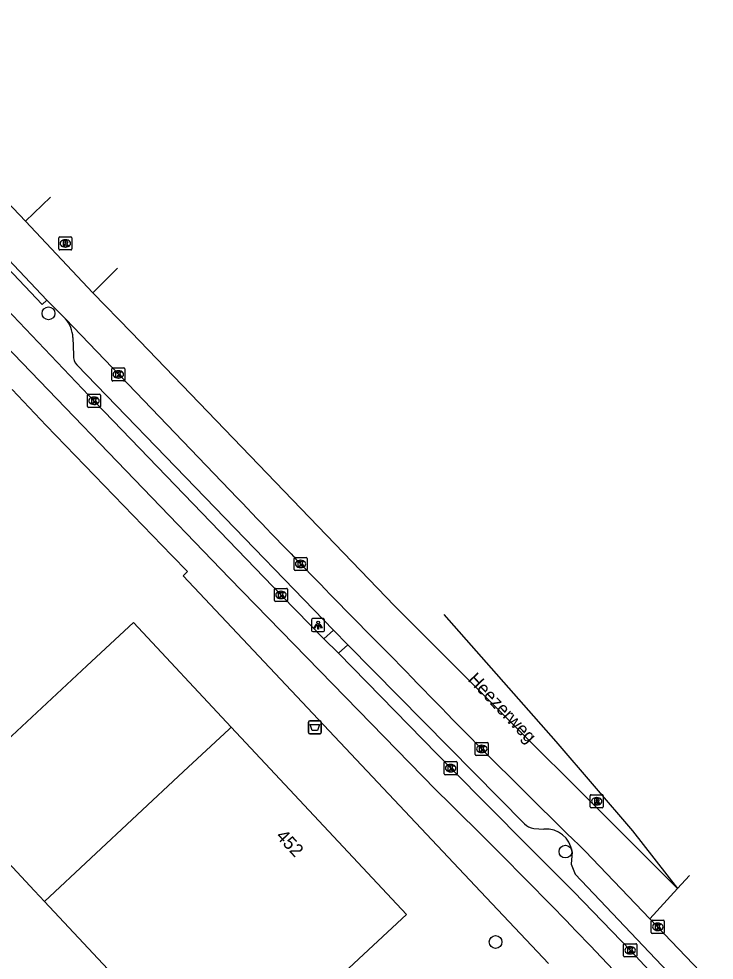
# Model space of a CAD drawing. Extents: x 162675 to 163482, y 379761 to 381227.
# Drawn here: x 163172.9 to 163226.1, y 381140.7 to 381212.8 of the extents above; entities that cross this region are included whole.
import ezdxf

# ---------------------------------------------------------------- set-up
doc = ezdxf.new("R2010")
doc.units = 0
for name, color, linetype in [('IMGEO_Afvalbak', 7, 'Continuous'), ('IMGEO_Boom', 7, 'Continuous'), ('IMGEO_Fietspad_gesloten', 7, 'Continuous'), ('IMGEO_Kolk', 7, 'Continuous'), ('IMGEO_Lichtpunt', 7, 'Continuous'), ('IMGEO_Openbare_ruimte_label', 7, 'Continuous'), ('IMGEO_Pand', 7, 'Continuous'), ('IMGEO_Pand_nummerreeks', 7, 'Continuous'), ('IMGEO_Parkeervlak_open', 7, 'Continuous'), ('IMGEO_Rijbaan_lokaal_gesloten', 7, 'Continuous'), ('IMGEO_Rioolput', 7, 'Continuous'), ('IMGEO_Voetpad_open', 7, 'Continuous')]:
    doc.layers.add(name, color=color, linetype=linetype)

msp = doc.modelspace()

# ---------------------------------------------------------------- linework, layer by layer
at = {"layer": 'IMGEO_Afvalbak'}
for p, q in [((163195.065, 381158.112), (163195.065, 381158.912)), ((163195.065, 381158.912), (163195.065, 381158.112)), ((163195.165, 381159.012), (163195.955, 381159.012)), ((163195.955, 381159.012), (163195.165, 381159.012)), ((163196.055, 381158.912), (163196.055, 381158.112)), ((163196.055, 381158.112), (163196.055, 381158.912)), ((163195.955, 381158.012), (163195.165, 381158.012)), ((163195.165, 381158.012), (163195.955, 381158.012))]:
    msp.add_line(p, q, dxfattribs=at)
msp.add_lwpolyline([(163195.208, 381158.726), (163195.912, 381158.726), (163195.763, 381158.256), (163195.357, 381158.256), (163195.208, 381158.726)], dxfattribs=at)
for centre, start, end in [((163195.165, 381158.912), 90, 180), ((163195.165, 381158.912), 90, 180), ((163195.955, 381158.912), 0, 90), ((163195.955, 381158.912), 360, 90), ((163195.165, 381158.112), 180, 270), ((163195.165, 381158.112), 180, 270), ((163195.955, 381158.112), 270, 0), ((163195.955, 381158.112), 270, 0)]:
    msp.add_arc(centre, 0.1, start, end, dxfattribs=at)
at = {"layer": 'IMGEO_Boom'}
for centre in [(163175.169, 381190.207), (163214.744, 381148.989), (163209.396, 381142.069)]:
    msp.add_circle(centre, 0.489, dxfattribs=at)
at = {"layer": 'IMGEO_Fietspad_gesloten'}
for points in [[(163196.244, 381165.283), (163193.035, 381168.573), (163178.747, 381183.413), (163164.651, 381198.209)], [(163204.799, 381153.749), (163189.021, 381169.931), (163167.194, 381192.6), (163163.242, 381196.786)], [(163196.244, 381165.283), (163197.359, 381164.18)], [(163254.065, 381104.768), (163246.857, 381112.468), (163234.1, 381126.005), (163219.744, 381141.388), (163215.395, 381145.9), (163211.799, 381149.501), (163205.99, 381155.343), (163197.359, 381164.18)], [(163442.528, 380900.205), (163438.582, 380904.399), (163403.356, 380942.043), (163381.324, 380965.637), (163349.187, 381000), (163303.348, 381049.029), (163302.54, 381049.896), (163269.7, 381085.146), (163222.96, 381135.118), (163217.057, 381141.357)]]:
    msp.add_lwpolyline(points, dxfattribs=at)
msp.add_arc((162825.277, 380766.073), 542.522, 43.76808, 45.60899, dxfattribs=at)
at = {"layer": 'IMGEO_Kolk'}
for p, q in [((163180.013, 381185.102), (163180.013, 381185.954)), ((163180.088, 381186.028), (163180.94, 381186.028)), ((163180.501, 381185.808), (163180.526, 381185.808)), ((163181.014, 381185.954), (163181.014, 381185.102)), ((163180.94, 381185.028), (163180.088, 381185.028)), ((163180.524, 381185.248), (163180.499, 381185.248)), ((163178.154, 381183.085), (163178.154, 381183.937)), ((163178.229, 381184.011), (163179.081, 381184.011)), ((163178.642, 381183.791), (163178.667, 381183.791)), ((163179.155, 381183.937), (163179.155, 381183.085)), ((163179.081, 381183.011), (163178.229, 381183.011)), ((163178.665, 381183.231), (163178.64, 381183.231)), ((163193.966, 381170.593), (163193.966, 381171.445)), ((163194.041, 381171.519), (163194.893, 381171.519)), ((163194.454, 381171.299), (163194.479, 381171.299)), ((163194.967, 381171.445), (163194.967, 381170.593)), ((163194.893, 381170.519), (163194.041, 381170.519)), ((163194.477, 381170.739), (163194.452, 381170.739)), ((163192.462, 381168.223), (163192.462, 381169.075)), ((163192.537, 381169.149), (163193.389, 381169.149)), ((163193.463, 381169.075), (163193.463, 381168.223)), ((163192.973, 381168.369), (163192.948, 381168.369)), ((163192.95, 381168.929), (163192.975, 381168.929)), ((163193.389, 381168.149), (163192.537, 381168.149)), ((163207.837, 381156.427), (163207.837, 381157.279)), ((163207.912, 381157.353), (163208.764, 381157.353)), ((163208.325, 381157.133), (163208.35, 381157.133)), ((163208.838, 381157.279), (163208.838, 381156.427)), ((163208.764, 381156.353), (163207.912, 381156.353)), ((163208.348, 381156.573), (163208.323, 381156.573)), ((163205.455, 381154.953), (163205.455, 381155.805)), ((163205.53, 381155.879), (163206.382, 381155.879)), ((163205.943, 381155.659), (163205.968, 381155.659)), ((163206.456, 381155.805), (163206.456, 381154.953)), ((163206.382, 381154.879), (163205.53, 381154.879)), ((163205.966, 381155.099), (163205.941, 381155.099)), ((163221.312, 381142.803), (163221.312, 381143.655)), ((163221.387, 381143.729), (163222.239, 381143.729)), ((163221.8, 381143.509), (163221.825, 381143.509)), ((163222.313, 381143.655), (163222.313, 381142.803)), ((163222.239, 381142.729), (163221.387, 381142.729)), ((163221.823, 381142.949), (163221.798, 381142.949)), ((163219.196, 381141.013), (163219.196, 381141.865)), ((163219.271, 381141.939), (163220.123, 381141.939)), ((163219.684, 381141.719), (163219.709, 381141.719)), ((163220.197, 381141.865), (163220.197, 381141.013)), ((163220.123, 381140.939), (163219.271, 381140.939)), ((163219.707, 381141.159), (163219.682, 381141.159))]:
    msp.add_line(p, q, dxfattribs=at)
for points in [[(163180.013, 381185.102), (163180.013, 381185.954)], [(163180.088, 381186.028), (163180.94, 381186.028)], [(163180.334, 381185.728), (163180.457, 381185.728), (163180.457, 381185.577), (163180.587, 381185.728), (163180.751, 381185.728), (163180.605, 381185.577), (163180.758, 381185.328), (163180.606, 381185.328), (163180.521, 381185.492), (163180.457, 381185.425), (163180.457, 381185.328), (163180.334, 381185.328), (163180.334, 381185.728)], [(163181.014, 381185.954), (163181.014, 381185.102)], [(163180.94, 381185.028), (163180.088, 381185.028)], [(163178.154, 381183.085), (163178.154, 381183.937)], [(163178.229, 381184.011), (163179.081, 381184.011)], [(163178.475, 381183.711), (163178.598, 381183.711), (163178.598, 381183.56), (163178.728, 381183.711), (163178.892, 381183.711), (163178.746, 381183.56), (163178.899, 381183.311), (163178.747, 381183.311), (163178.662, 381183.475), (163178.598, 381183.408), (163178.598, 381183.311), (163178.475, 381183.311), (163178.475, 381183.711)], [(163179.155, 381183.937), (163179.155, 381183.085)], [(163179.081, 381183.011), (163178.229, 381183.011)], [(163193.966, 381170.593), (163193.966, 381171.445)], [(163194.041, 381171.519), (163194.893, 381171.519)], [(163194.287, 381171.219), (163194.41, 381171.219), (163194.41, 381171.068), (163194.54, 381171.219), (163194.704, 381171.219), (163194.558, 381171.068), (163194.711, 381170.819), (163194.559, 381170.819), (163194.474, 381170.983), (163194.41, 381170.916), (163194.41, 381170.819), (163194.287, 381170.819), (163194.287, 381171.219)], [(163194.967, 381171.445), (163194.967, 381170.593)], [(163194.893, 381170.519), (163194.041, 381170.519)], [(163192.462, 381168.223), (163192.462, 381169.075)], [(163192.537, 381169.149), (163193.389, 381169.149)], [(163193.463, 381169.075), (163193.463, 381168.223)], [(163192.783, 381168.849), (163192.906, 381168.849), (163192.906, 381168.698), (163193.036, 381168.849), (163193.2, 381168.849), (163193.054, 381168.698), (163193.207, 381168.449), (163193.055, 381168.449), (163192.97, 381168.613), (163192.906, 381168.546), (163192.906, 381168.449), (163192.783, 381168.449), (163192.783, 381168.849)], [(163193.389, 381168.149), (163192.537, 381168.149)], [(163207.837, 381156.427), (163207.837, 381157.279)], [(163207.912, 381157.353), (163208.764, 381157.353)], [(163208.158, 381157.053), (163208.281, 381157.053), (163208.281, 381156.902), (163208.411, 381157.053), (163208.575, 381157.053), (163208.429, 381156.902), (163208.582, 381156.653), (163208.43, 381156.653), (163208.345, 381156.817), (163208.281, 381156.75), (163208.281, 381156.653), (163208.158, 381156.653), (163208.158, 381157.053)], [(163208.838, 381157.279), (163208.838, 381156.427)], [(163208.764, 381156.353), (163207.912, 381156.353)], [(163205.455, 381154.953), (163205.455, 381155.805)], [(163205.53, 381155.879), (163206.382, 381155.879)], [(163205.776, 381155.579), (163205.899, 381155.579), (163205.899, 381155.428), (163206.029, 381155.579), (163206.193, 381155.579), (163206.047, 381155.428), (163206.2, 381155.179), (163206.048, 381155.179), (163205.963, 381155.343), (163205.899, 381155.276), (163205.899, 381155.179), (163205.776, 381155.179), (163205.776, 381155.579)], [(163206.456, 381155.805), (163206.456, 381154.953)], [(163206.382, 381154.879), (163205.53, 381154.879)], [(163221.312, 381142.803), (163221.312, 381143.655)], [(163221.387, 381143.729), (163222.239, 381143.729)], [(163221.633, 381143.429), (163221.756, 381143.429), (163221.756, 381143.278), (163221.886, 381143.429), (163222.05, 381143.429), (163221.904, 381143.278), (163222.057, 381143.029), (163221.905, 381143.029), (163221.82, 381143.193), (163221.756, 381143.126), (163221.756, 381143.029), (163221.633, 381143.029), (163221.633, 381143.429)], [(163222.313, 381143.655), (163222.313, 381142.803)], [(163222.239, 381142.729), (163221.387, 381142.729)], [(163219.196, 381141.013), (163219.196, 381141.865)], [(163219.271, 381141.939), (163220.123, 381141.939)], [(163219.517, 381141.639), (163219.64, 381141.639), (163219.64, 381141.488), (163219.77, 381141.639), (163219.934, 381141.639), (163219.788, 381141.488), (163219.941, 381141.239), (163219.789, 381141.239), (163219.704, 381141.403), (163219.64, 381141.336), (163219.64, 381141.239), (163219.517, 381141.239), (163219.517, 381141.639)], [(163220.197, 381141.865), (163220.197, 381141.013)], [(163220.123, 381140.939), (163219.271, 381140.939)]]:
    msp.add_lwpolyline(points, dxfattribs=at)
for centre, start, end in [((163180.09, 381185.952), 91.55205, 178.44795), ((163180.09, 381185.952), 91.55205, 178.44795), ((163180.938, 381185.952), 1.55205, 88.44795), ((163180.938, 381185.952), 1.55205, 88.44795), ((163180.09, 381185.104), 181.55205, 268.44795), ((163180.09, 381185.104), 181.55205, 268.44795), ((163180.938, 381185.104), 271.55205, 358.44795), ((163180.938, 381185.104), 271.55205, 358.44795), ((163178.231, 381183.935), 91.55205, 178.44795), ((163178.231, 381183.935), 91.55205, 178.44795), ((163179.079, 381183.935), 1.55205, 88.44795), ((163179.079, 381183.935), 1.55205, 88.44795), ((163178.231, 381183.087), 181.55205, 268.44795), ((163178.231, 381183.087), 181.55205, 268.44795), ((163179.079, 381183.087), 271.55205, 358.44795), ((163179.079, 381183.087), 271.55205, 358.44795), ((163194.043, 381171.443), 91.55205, 178.44795), ((163194.043, 381171.443), 91.55205, 178.44795), ((163194.891, 381171.443), 1.55205, 88.44795), ((163194.891, 381171.443), 1.55205, 88.44795), ((163194.043, 381170.595), 181.55205, 268.44795), ((163194.043, 381170.595), 181.55205, 268.44795), ((163194.891, 381170.595), 271.55205, 358.44795), ((163194.891, 381170.595), 271.55205, 358.44795), ((163192.539, 381169.073), 91.55205, 178.44795), ((163192.539, 381169.073), 91.55205, 178.44795), ((163193.387, 381169.073), 1.55205, 88.44795), ((163193.387, 381169.073), 1.55205, 88.44795), ((163192.539, 381168.225), 181.55205, 268.44795), ((163192.539, 381168.225), 181.55205, 268.44795), ((163193.387, 381168.225), 271.55205, 358.44795), ((163193.387, 381168.225), 271.55205, 358.44795), ((163207.914, 381157.277), 91.55205, 178.44795), ((163207.914, 381157.277), 91.55205, 178.44795), ((163208.762, 381157.277), 1.55205, 88.44795), ((163208.762, 381157.277), 1.55205, 88.44795), ((163207.914, 381156.429), 181.55205, 268.44795), ((163207.914, 381156.429), 181.55205, 268.44795), ((163208.762, 381156.429), 271.55205, 358.44795), ((163208.762, 381156.429), 271.55205, 358.44795), ((163205.532, 381155.803), 91.55205, 178.44795), ((163205.532, 381155.803), 91.55205, 178.44795), ((163206.38, 381155.803), 1.55205, 88.44795), ((163206.38, 381155.803), 1.55205, 88.44795), ((163205.532, 381154.955), 181.55205, 268.44795), ((163205.532, 381154.955), 181.55205, 268.44795), ((163206.38, 381154.955), 271.55205, 358.44795), ((163206.38, 381154.955), 271.55205, 358.44795), ((163221.389, 381143.653), 91.55205, 178.44795), ((163221.389, 381143.653), 91.55205, 178.44795), ((163222.237, 381143.653), 1.55205, 88.44795), ((163222.237, 381143.653), 1.55205, 88.44795), ((163221.389, 381142.805), 181.55205, 268.44795), ((163221.389, 381142.805), 181.55205, 268.44795), ((163222.237, 381142.805), 271.55205, 358.44795), ((163222.237, 381142.805), 271.55205, 358.44795), ((163219.273, 381141.863), 91.55205, 178.44795), ((163219.273, 381141.863), 91.55205, 178.44795), ((163220.121, 381141.863), 1.55205, 88.44795), ((163220.121, 381141.863), 1.55205, 88.44795), ((163219.273, 381141.015), 181.55205, 268.44795), ((163219.273, 381141.015), 181.55205, 268.44795), ((163220.121, 381141.015), 271.55205, 358.44795), ((163220.121, 381141.015), 271.55205, 358.44795)]:
    msp.add_arc(centre, 0.0765, start, end, dxfattribs=at)
for centre, major_axis, ratio, start_param, end_param in [((163180.5, 381185.528), (-0.387, 0.002), 0.722429, 4.712389, 7.853982), ((163180.525, 381185.528), (-0.39, 0.002), 0.717154, 1.570796, 4.712389), ((163178.641, 381183.511), (-0.387, 0.002), 0.722429, 4.712389, 7.853982), ((163178.666, 381183.511), (-0.39, 0.002), 0.717154, 1.570796, 4.712389), ((163194.453, 381171.019), (-0.387, 0.002), 0.722429, 4.712389, 7.853982), ((163194.478, 381171.019), (-0.39, 0.002), 0.717154, 1.570796, 4.712389), ((163192.949, 381168.649), (-0.387, 0.002), 0.722429, 4.712389, 7.853982), ((163192.974, 381168.649), (-0.39, 0.002), 0.717154, 1.570796, 4.712389), ((163208.324, 381156.853), (-0.387, 0.002), 0.722429, 4.712389, 7.853982), ((163208.349, 381156.853), (-0.39, 0.002), 0.717154, 1.570796, 4.712389), ((163205.942, 381155.379), (-0.387, 0.002), 0.722429, 4.712389, 7.853982), ((163205.967, 381155.379), (-0.39, 0.002), 0.717154, 1.570796, 4.712389), ((163221.799, 381143.229), (-0.387, 0.002), 0.722429, 4.712389, 7.853982), ((163221.824, 381143.229), (-0.39, 0.002), 0.717154, 1.570796, 4.712389), ((163219.683, 381141.439), (-0.387, 0.002), 0.722429, 4.712389, 7.853982), ((163219.708, 381141.439), (-0.39, 0.002), 0.717154, 1.570796, 4.712389)]:
    msp.add_ellipse(centre, major_axis=major_axis, ratio=ratio, start_param=start_param, end_param=end_param, dxfattribs=at)
at = {"layer": 'IMGEO_Lichtpunt'}
for p, q in [((163195.308, 381166.735), (163195.308, 381165.928)), ((163195.308, 381166.735), (163195.308, 381165.928)), ((163196.21, 381166.83), (163195.402, 381166.83)), ((163196.21, 381166.83), (163195.402, 381166.83)), ((163196.304, 381165.928), (163196.304, 381166.735)), ((163196.304, 381165.928), (163196.304, 381166.735)), ((163195.402, 381165.834), (163196.21, 381165.834)), ((163195.402, 381165.834), (163196.21, 381165.834))]:
    msp.add_line(p, q, dxfattribs=at)
for points in [[(163195.682, 381166.399), (163195.721, 381166.371), (163195.533, 381166.109), (163195.495, 381166.136), (163195.682, 381166.399)], [(163195.784, 381166.351), (163195.831, 381166.351), (163195.831, 381166.029), (163195.784, 381166.029), (163195.784, 381166.351)], [(163195.894, 381166.371), (163195.932, 381166.398), (163196.119, 381166.136), (163196.08, 381166.108), (163195.894, 381166.371)]]:
    msp.add_lwpolyline(points, dxfattribs=at)
msp.add_circle((163195.807, 381166.533), 0.0994, dxfattribs=at)
for centre, start, end in [((163195.402, 381166.735), 90, 180), ((163195.402, 381166.735), 90, 180), ((163196.21, 381166.735), 0, 90), ((163196.21, 381166.735), 0, 90), ((163195.402, 381165.928), 180, 270), ((163195.402, 381165.928), 180, 270), ((163196.21, 381165.928), 270, 0), ((163196.21, 381165.928), 270, 360)]:
    msp.add_arc(centre, 0.0946, start, end, dxfattribs=at)
at = {"layer": 'IMGEO_Pand'}
for points in [[(163189.159, 381158.528), (163181.665, 381166.536), (163178.103, 381163.214), (163167.364, 381153.198), (163174.102, 381145.989), (163174.872, 381145.158)], [(163174.872, 381145.158), (163185.509, 381155.112), (163188.999, 381158.378), (163189.159, 381158.528)], [(163189.159, 381158.528), (163202.583, 381144.183), (163198.932, 381140.767), (163188.295, 381130.814), (163174.872, 381145.158)]]:
    msp.add_lwpolyline(points, dxfattribs=at)
at = {"layer": 'IMGEO_Parkeervlak_open'}
for points in [[(163177.033, 381188.364), (163177.087, 381187)], [(163177.33, 381186.268), (163196.998, 381165.958)], [(163198.075, 381164.83), (163211.602, 381151.113)], [(163212.311, 381150.769), (163213.1, 381150.714)], [(163215.253, 381148.98), (163215.183, 381148.016), (163215.477, 381147.261), (163223.073, 381139.269)]]:
    msp.add_lwpolyline(points, dxfattribs=at)
for centre, radius, start, end in [((163174.83, 381188.315), 2.203, 1.2639, 41.90786), ((163178.096, 381186.929), 1.012, 175.96151, 220.76744), ((163212.41, 381151.875), 1.111, 223.34205, 264.89351), ((163213.279, 381148.733), 1.989, 7.13945, 95.16546)]:
    msp.add_arc(centre, radius, start, end, dxfattribs=at)
at = {"layer": 'IMGEO_Rijbaan_lokaal_gesloten'}
for points in [[(163158.672, 381212.762), (163173.409, 381197.28)], [(163166.594, 381200.148), (163175.05, 381191.223)], [(163173.409, 381197.28), (163175.331, 381199.101)], [(163173.409, 381197.28), (163178.553, 381191.775)], [(163178.553, 381191.775), (163180.456, 381193.658)], [(163178.553, 381191.775), (163181.508, 381188.764), (163201.659, 381167.809), (163209.449, 381160.031), (163218.198, 381151.298), (163223.334, 381146.17)], [(163175.05, 381191.223), (163176.47, 381189.787)], [(163176.47, 381189.787), (163189.642, 381176.061)], [(163205.425, 381167.139), (163214.011, 381157.42), (163219.883, 381150.574), (163223.334, 381146.17)], [(163216.248, 381149.035), (163221.2, 381143.841)], [(163223.334, 381146.17), (163224.239, 381147.157)], [(163223.334, 381146.17), (163221.2, 381143.841)], [(163221.2, 381143.841), (163226.152, 381138.647), (163256.222, 381106.354)]]:
    msp.add_lwpolyline(points, dxfattribs=at)
for centre, radius, start, end in [((163693.816, 381653.982), 694.694, 223.468766, 224.889553), ((163626.709, 381572.111), 589.467, 223.855007, 225.867058)]:
    msp.add_arc(centre, radius, start, end, dxfattribs=at)
at = {"layer": 'IMGEO_Rioolput'}
for p, q in [((163175.96, 381195.136), (163175.96, 381195.988)), ((163176.035, 381196.062), (163176.887, 381196.062)), ((163176.448, 381195.842), (163176.473, 381195.842)), ((163176.961, 381195.988), (163176.961, 381195.136)), ((163176.887, 381195.062), (163176.035, 381195.062)), ((163176.471, 381195.282), (163176.446, 381195.282)), ((163216.639, 381152.421), (163216.639, 381153.273)), ((163216.714, 381153.347), (163217.566, 381153.347)), ((163217.64, 381153.273), (163217.64, 381152.421)), ((163217.15, 381152.567), (163217.125, 381152.567)), ((163217.127, 381153.127), (163217.152, 381153.127)), ((163217.566, 381152.347), (163216.714, 381152.347))]:
    msp.add_line(p, q, dxfattribs=at)
for points in [[(163175.96, 381195.136), (163175.96, 381195.988)], [(163176.035, 381196.062), (163176.887, 381196.062)], [(163176.549, 381195.76), (163176.297, 381195.762), (163176.297, 381195.362)], [(163176.475, 381195.681), (163176.421, 381195.681), (163176.421, 381195.6)], [(163176.961, 381195.988), (163176.961, 381195.136)], [(163176.887, 381195.062), (163176.035, 381195.062)], [(163176.297, 381195.362), (163176.421, 381195.362), (163176.421, 381195.524), (163176.432, 381195.524)], [(163176.421, 381195.6), (163176.473, 381195.6)], [(163176.479, 381195.495), (163176.55, 381195.362), (163176.69, 381195.362), (163176.625, 381195.488)], [(163216.639, 381152.421), (163216.639, 381153.273)], [(163216.714, 381153.347), (163217.566, 381153.347)], [(163217.64, 381153.273), (163217.64, 381152.421)], [(163217.228, 381153.045), (163216.976, 381153.047), (163216.976, 381152.647)], [(163216.976, 381152.647), (163217.1, 381152.647), (163217.1, 381152.809), (163217.111, 381152.809)], [(163217.154, 381152.966), (163217.1, 381152.966), (163217.1, 381152.885)], [(163217.1, 381152.885), (163217.152, 381152.885)], [(163217.158, 381152.78), (163217.229, 381152.647), (163217.369, 381152.647), (163217.304, 381152.773)], [(163217.566, 381152.347), (163216.714, 381152.347)]]:
    msp.add_lwpolyline(points, dxfattribs=at)
for centre, radius, start, end in [((163176.037, 381195.986), 0.0765, 91.55205, 178.44795), ((163176.037, 381195.986), 0.0765, 91.55205, 178.44795), ((163176.481, 381195.585), 0.0964, 77.00612, 93.18647), ((163176.495, 381195.642), 0.0378, 276.66336, 79.67722), ((163176.548, 381195.65), 0.109, 350.36119, 89.41601), ((163176.885, 381195.986), 0.0765, 1.55205, 88.44795), ((163176.885, 381195.986), 0.0765, 1.55205, 88.44795), ((163176.037, 381195.138), 0.0765, 181.55205, 268.44795), ((163176.037, 381195.138), 0.0765, 181.55205, 268.44795), ((163176.431, 381195.471), 0.0533, 26.02933, 88.69889), ((163176.457, 381195.789), 0.19, 274.7715, 282.96867), ((163176.546, 381195.65), 0.112, 277.58423, 350.98172), ((163176.53, 381195.435), 0.108, 29.51342, 73.79051), ((163176.885, 381195.138), 0.0765, 271.55205, 358.44795), ((163176.885, 381195.138), 0.0765, 271.55205, 358.44795), ((163216.716, 381153.271), 0.0765, 91.55205, 178.44795), ((163216.716, 381153.271), 0.0765, 91.55205, 178.44795), ((163217.564, 381153.271), 0.0765, 1.55205, 88.44795), ((163217.564, 381153.271), 0.0765, 1.55205, 88.44795), ((163216.716, 381152.423), 0.0765, 181.55205, 268.44795), ((163216.716, 381152.423), 0.0765, 181.55205, 268.44795), ((163217.11, 381152.756), 0.0533, 26.02933, 88.69889), ((163217.136, 381153.074), 0.19, 274.7715, 282.96867), ((163217.16, 381152.87), 0.0964, 77.00612, 93.18647), ((163217.174, 381152.927), 0.0378, 276.66336, 79.67722), ((163217.227, 381152.935), 0.109, 350.36119, 89.41601), ((163217.225, 381152.935), 0.112, 277.58423, 350.98172), ((163217.209, 381152.72), 0.108, 29.51342, 73.79051), ((163217.564, 381152.423), 0.0765, 271.55205, 358.44795), ((163217.564, 381152.423), 0.0765, 271.55205, 358.44795)]:
    msp.add_arc(centre, radius, start, end, dxfattribs=at)
for centre, major_axis, ratio, start_param, end_param in [((163176.447, 381195.562), (-0.387, 0.002), 0.722429, 4.712389, 7.853982), ((163176.472, 381195.562), (-0.39, 0.002), 0.717154, 1.570796, 4.712389), ((163217.126, 381152.847), (-0.387, 0.002), 0.722429, 4.712389, 7.853982), ((163217.151, 381152.847), (-0.39, 0.002), 0.717154, 1.570796, 4.712389)]:
    msp.add_ellipse(centre, major_axis=major_axis, ratio=ratio, start_param=start_param, end_param=end_param, dxfattribs=at)
at = {"layer": 'IMGEO_Voetpad_open'}
for points in [[(163166.232, 381199.805), (163174.688, 381190.88), (163175.05, 381191.223)], [(163172.387, 381184.371), (163174.993, 381181.631), (163184.607, 381171.672), (163185.803, 381170.433), (163185.468, 381170.109), (163207.843, 381146.366), (163213.453, 381140.413)], [(163196.998, 381165.958), (163196.244, 381165.283)], [(163196.998, 381165.958), (163198.075, 381164.83)], [(163197.359, 381164.18), (163198.075, 381164.83)]]:
    msp.add_lwpolyline(points, dxfattribs=at)

# ---------------------------------------------------------------- texts
at = {"layer": 'IMGEO_Openbare_ruimte_label'}
msp.add_text('Heezerweg', height=1, rotation=313.62257, dxfattribs=at).set_placement((163207.222, 381162.111))
at = {"layer": 'IMGEO_Pand_nummerreeks'}
msp.add_text('452', height=1, rotation=313.1004, dxfattribs=at).set_placement((163192.533, 381150.123))

doc.saveas('drawing.dxf')
